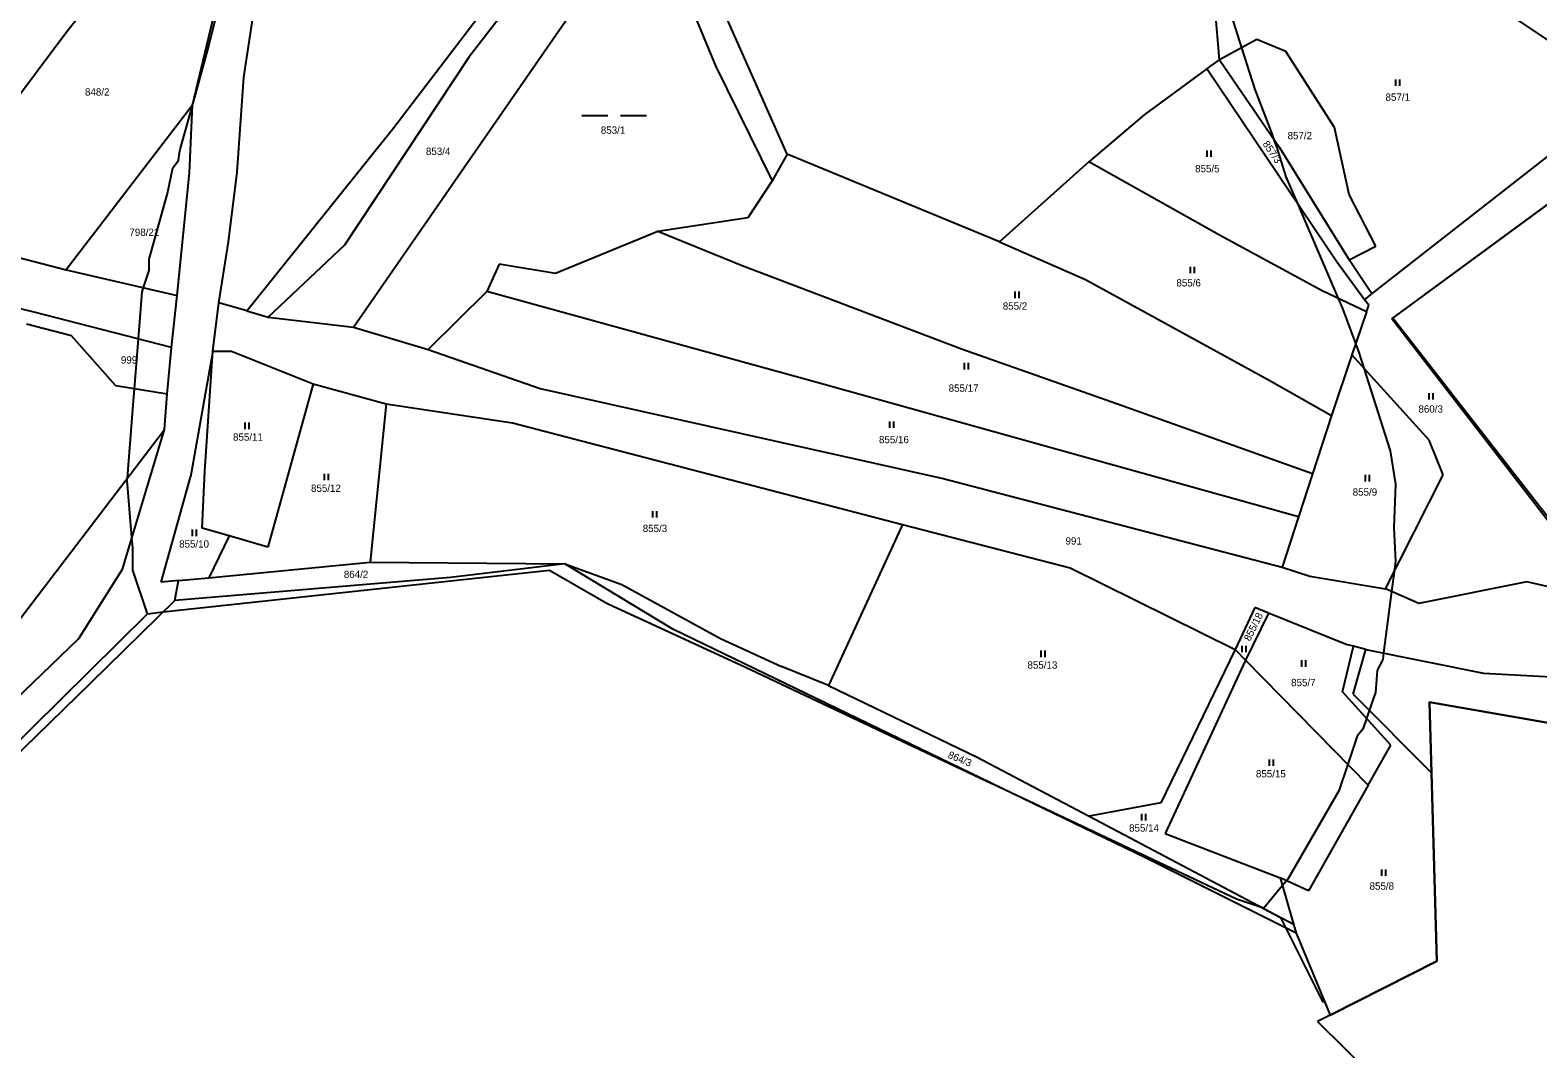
# Model space of a CAD drawing. Extents: x -749173 to -746119, y -1132678 to -1130338.
# Drawn here: x -747634.7 to -747283.8, y -1131870.4 to -1131633.3 of the extents above; entities that cross this region are included whole.
import ezdxf

# ---------------------------------------------------------------- set-up
doc = ezdxf.new("R2010")
doc.units = 0
for name, color, linetype in [('Vrstva 1', 7, 'Continuous'), ('Vrstva 18', 7, 'Continuous'), ('Vrstva 25', 7, 'Continuous'), ('Vrstva 52', 7, 'Continuous'), ('Vrstva 6', 7, 'Continuous')]:
    doc.layers.add(name, color=color, linetype=linetype)

msp = doc.modelspace()

# ---------------------------------------------------------------- linework, layer by layer
at = {"layer": 'Vrstva 1'}
for points in [[(-747357.88, -1131640.25), (-747361.08, -1131602.88)], [(-747596.84, -1131650.77), (-747587.27, -1131610.47)], [(-747550, -1131656.02), (-747518.42, -1131614.59)], [(-747512.18, -1131613.29), (-747532.53, -1131639.52)], [(-747458.45, -1131662.17), (-747478.47, -1131617.02)], [(-747484.66, -1131618.77), (-747475.19, -1131641.65)], [(-747559.41, -1131702.48), (-747504.69, -1131623.44)], [(-747584.9, -1131644.26), (-747582.84, -1131630.56)], [(-747290.52, -1131629.64), (-747262.86, -1131648.18)], [(-747349.2, -1131635.5), (-747357.88, -1131640.25)], [(-747342.45, -1131638.32), (-747349.2, -1131635.5)], [(-747532.53, -1131639.52), (-747561.47, -1131683.37)], [(-747331.11, -1131655.97), (-747342.45, -1131638.32)], [(-747475.19, -1131641.65), (-747462.01, -1131668.39)], [(-747360.8, -1131642.37), (-747375.43, -1131653.05)], [(-747360.8, -1131642.37), (-747357.88, -1131640.25)], [(-747330.67, -1131687.18), (-747360.8, -1131642.37)], [(-747357.88, -1131640.25), (-747343.93, -1131660.68)], [(-747586.46, -1131666.42), (-747584.9, -1131644.26)], [(-747322.41, -1131694.68), (-747262.86, -1131648.18)], [(-747597.6, -1131666.57), (-747596.84, -1131650.77)], [(-747375.43, -1131653.05), (-747388.27, -1131663.97)], [(-747584.22, -1131698.64), (-747550, -1131656.02)], [(-747327.7, -1131671.61), (-747331.11, -1131655.97)], [(-747317.79, -1131700.5), (-747257.91, -1131656.57)], [(-747458.45, -1131662.17), (-747462.01, -1131668.39)], [(-747409.06, -1131682.61), (-747458.45, -1131662.17)], [(-747388.27, -1131663.97), (-747409.06, -1131682.61)], [(-747357.85, -1131681.06), (-747388.27, -1131663.97)], [(-747343.93, -1131660.68), (-747327.68, -1131686.79)], [(-747600.45, -1131695.05), (-747597.6, -1131666.57)], [(-747588.52, -1131682.57), (-747586.46, -1131666.42)], [(-747462.01, -1131668.39), (-747467.61, -1131677.03)], [(-747321.53, -1131683.62), (-747327.7, -1131671.61)], [(-747467.61, -1131677.03), (-747488.58, -1131680.22)], [(-747660.92, -1131680.14), (-747626.3, -1131689.08)], [(-747488.58, -1131680.22), (-747512.4, -1131689.95)], [(-747334, -1131693.97), (-747357.85, -1131681.06)], [(-747590.72, -1131696.79), (-747588.52, -1131682.57)], [(-747561.47, -1131683.37), (-747579.28, -1131700.12)], [(-747409.06, -1131682.61), (-747389.09, -1131691.38)], [(-747327.68, -1131686.79), (-747321.53, -1131683.62)], [(-747525.49, -1131687.82), (-747528.4, -1131694.14)], [(-747512.4, -1131689.95), (-747525.49, -1131687.82)], [(-747324.17, -1131696.09), (-747330.67, -1131687.18)], [(-747322.41, -1131694.68), (-747327.68, -1131686.79)], [(-747633.7, -1131698.94), (-747668.66, -1131690.61)], [(-747626.3, -1131689.08), (-747600.45, -1131695.05)], [(-747389.09, -1131691.38), (-747346.34, -1131714.79)], [(-747601.8, -1131707.17), (-747600.45, -1131695.05)], [(-747528.4, -1131694.14), (-747542.02, -1131707.68)], [(-747323.64, -1131698.92), (-747334, -1131693.97)], [(-747324.17, -1131696.09), (-747322.41, -1131694.68)], [(-747601.8, -1131707.17), (-747633.7, -1131698.94)], [(-747592.13, -1131708.07), (-747590.72, -1131696.79)], [(-747584.22, -1131698.64), (-747590.72, -1131696.79)], [(-747584.22, -1131698.64), (-747579.28, -1131700.12)], [(-747323.64, -1131698.92), (-747327.11, -1131708.86)], [(-747323.11, -1131697.35), (-747324.17, -1131696.09)], [(-747323.64, -1131698.92), (-747323.11, -1131697.35)], [(-747625.03, -1131704.45), (-747635.51, -1131701.73)], [(-747579.28, -1131700.12), (-747559.41, -1131702.48)], [(-747559.41, -1131702.48), (-747542.02, -1131707.68)], [(-747267.01, -1131766.16), (-747317.79, -1131700.5)], [(-747614.7, -1131716.11), (-747625.03, -1131704.45)], [(-747602.77, -1131718.05), (-747601.8, -1131707.17)], [(-747592.13, -1131708.07), (-747594.14, -1131719.37)], [(-747592.13, -1131708.07), (-747587.81, -1131708.07)], [(-747587.81, -1131708.07), (-747568.8, -1131715.62)], [(-747542.02, -1131707.68), (-747515.95, -1131716.72)], [(-747327.11, -1131708.86), (-747331.81, -1131723.04)], [(-747309.11, -1131728.78), (-747327.11, -1131708.86)], [(-747602.77, -1131718.05), (-747614.7, -1131716.11)], [(-747568.8, -1131715.62), (-747551.8, -1131720.33)], [(-747346.34, -1131714.79), (-747331.81, -1131723.04)], [(-747603.39, -1131726.29), (-747602.77, -1131718.05)], [(-747594.14, -1131719.37), (-747597.33, -1131737.34)], [(-747515.95, -1131716.72), (-747422.18, -1131737.69)], [(-747551.8, -1131720.33), (-747522.4, -1131724.74)], [(-747331.81, -1131723.04), (-747336.24, -1131736.62)], [(-747646.92, -1131783.21), (-747603.39, -1131726.29)], [(-747613.18, -1131758.77), (-747603.39, -1131726.29)], [(-747522.4, -1131724.74), (-747431.62, -1131748.34)], [(-747305.82, -1131736.8), (-747309.11, -1131728.78)], [(-747604.15, -1131761.78), (-747597.33, -1131737.34)], [(-747422.18, -1131737.69), (-747343.31, -1131758.31)], [(-747336.24, -1131736.62), (-747339.49, -1131746.59)], [(-747319.28, -1131763.36), (-747305.82, -1131736.8)], [(-747339.49, -1131746.59), (-747343.31, -1131758.31)], [(-747431.62, -1131748.34), (-747392.64, -1131758.47)], [(-747623.35, -1131774.87), (-747613.18, -1131758.77)], [(-747593.06, -1131760.75), (-747555.53, -1131757.15)], [(-747555.53, -1131757.15), (-747510.21, -1131757.54)], [(-747510.21, -1131757.54), (-747536.87, -1131760.7)], [(-747510.21, -1131757.54), (-747496.95, -1131762.32)], [(-747485.07, -1131772.73), (-747510.21, -1131757.54)], [(-747392.64, -1131758.47), (-747354.27, -1131777.45)], [(-747343.31, -1131758.31), (-747336.85, -1131760.37)], [(-747600.14, -1131761.43), (-747604.15, -1131761.78)], [(-747536.87, -1131760.7), (-747601, -1131766.04)], [(-747601, -1131766.04), (-747600.14, -1131761.43)], [(-747600.14, -1131761.43), (-747593.06, -1131760.75)], [(-747496.95, -1131762.32), (-747474.01, -1131774.9)], [(-747336.85, -1131760.37), (-747319.28, -1131763.36)], [(-747286.37, -1131761.74), (-747311.5, -1131766.78)], [(-747267.01, -1131766.16), (-747286.37, -1131761.74)], [(-747311.5, -1131766.78), (-747319.28, -1131763.36)], [(-747601, -1131766.04), (-747620.58, -1131785.29)], [(-747349.64, -1131767.7), (-747354.27, -1131777.45)], [(-747346.48, -1131768.98), (-747349.64, -1131767.7)], [(-747328.4, -1131776.31), (-747346.48, -1131768.98)], [(-747375.12, -1131825.91), (-747485.07, -1131772.73)], [(-747651.15, -1131801.66), (-747623.35, -1131774.87)], [(-747474.01, -1131774.9), (-747459.79, -1131781.43)], [(-747326.7, -1131776.72), (-747328.4, -1131776.31)], [(-747354.27, -1131777.45), (-747351.83, -1131779.93)], [(-747329.29, -1131787.29), (-747326.7, -1131776.72)], [(-747326.78, -1131787.84), (-747323.8, -1131777.42)], [(-747323.8, -1131777.42), (-747326.7, -1131776.72)], [(-747323.8, -1131777.42), (-747296.48, -1131782.93)], [(-747448.86, -1131785.87), (-747459.79, -1131781.43)], [(-747351.83, -1131779.93), (-747323.26, -1131809)], [(-747296.48, -1131782.93), (-747266.19, -1131784.57)], [(-747620.58, -1131785.29), (-747683.25, -1131846.23)], [(-747448.86, -1131785.87), (-747414.25, -1131802.49)], [(-747318.03, -1131799.74), (-747329.29, -1131787.29)], [(-747326.78, -1131787.84), (-747308.51, -1131806.18)], [(-747274.72, -1131795.65), (-747308.97, -1131789.7)], [(-747308.97, -1131789.7), (-747308.51, -1131806.18)], [(-747323.26, -1131809), (-747318.03, -1131799.74)], [(-747414.25, -1131802.49), (-747388.18, -1131816.27)], [(-747308.51, -1131806.18), (-747307.27, -1131850)], [(-747323.26, -1131809), (-747337.16, -1131833.58)], [(-747388.18, -1131816.27), (-747340.66, -1131841.38)], [(-747340.05, -1131843.48), (-747375.12, -1131825.91)], [(-747337.16, -1131833.58), (-747343.77, -1131830.6)], [(-747343.77, -1131830.6), (-747340.66, -1131841.38)], [(-747340.66, -1131841.38), (-747340.05, -1131843.48)], [(-747340.05, -1131843.48), (-747332.1, -1131862.53)], [(-747307.27, -1131850), (-747332.1, -1131862.53)], [(-747332.1, -1131862.53), (-747335.11, -1131864.05)], [(-747335.11, -1131864.05), (-747316.12, -1131882.74)]]:
    msp.add_lwpolyline(points, dxfattribs=at)
at = {"layer": 'Vrstva 25'}
for p, q in [((-747316.92, -1131644.82), (-747316.92, -1131646.32)), ((-747315.92, -1131646.32), (-747315.92, -1131644.82)), ((-747506.25, -1131653.22), (-747500.25, -1131653.22)), ((-747497.25, -1131653.22), (-747491.25, -1131653.22)), ((-747360.81, -1131661.35), (-747360.81, -1131662.85)), ((-747359.81, -1131662.85), (-747359.81, -1131661.35)), ((-747364.67, -1131688.4), (-747364.67, -1131689.9)), ((-747363.67, -1131689.9), (-747363.67, -1131688.4)), ((-747405.52, -1131694.18), (-747405.52, -1131695.68)), ((-747404.52, -1131695.68), (-747404.52, -1131694.18)), ((-747417.28, -1131710.77), (-747417.28, -1131712.27)), ((-747416.28, -1131712.27), (-747416.28, -1131710.77)), ((-747309.18, -1131717.8), (-747309.18, -1131719.3)), ((-747308.18, -1131719.3), (-747308.18, -1131717.8)), ((-747584.72, -1131724.67), (-747584.72, -1131726.17)), ((-747583.72, -1131726.17), (-747583.72, -1131724.67)), ((-747434.66, -1131724.39), (-747434.66, -1131725.89)), ((-747433.66, -1131725.89), (-747433.66, -1131724.39)), ((-747566.2, -1131736.58), (-747566.2, -1131738.08)), ((-747565.2, -1131738.08), (-747565.2, -1131736.58)), ((-747324, -1131736.84), (-747324, -1131738.34)), ((-747323, -1131738.34), (-747323, -1131736.84)), ((-747489.84, -1131745.27), (-747489.84, -1131746.77)), ((-747488.84, -1131746.77), (-747488.84, -1131745.27)), ((-747596.93, -1131749.55), (-747596.93, -1131751.05)), ((-747595.93, -1131751.05), (-747595.93, -1131749.55)), ((-747399.45, -1131777.72), (-747399.45, -1131779.22)), ((-747398.45, -1131779.22), (-747398.45, -1131777.72)), ((-747352.67, -1131776.61), (-747352.67, -1131778.11)), ((-747351.67, -1131778.11), (-747351.67, -1131776.61)), ((-747338.8, -1131779.96), (-747338.8, -1131781.46)), ((-747337.8, -1131781.46), (-747337.8, -1131779.96)), ((-747346.32, -1131803.02), (-747346.32, -1131804.52)), ((-747345.32, -1131804.52), (-747345.32, -1131803.02)), ((-747376.06, -1131815.72), (-747376.06, -1131817.22)), ((-747375.06, -1131817.22), (-747375.06, -1131815.72)), ((-747320.16, -1131828.66), (-747320.16, -1131830.16)), ((-747319.16, -1131830.16), (-747319.16, -1131828.66))]:
    msp.add_line(p, q, dxfattribs=at)
at = {"layer": 'Vrstva 52'}
for points in [[(-747372.5, -1131565), (-747370.5, -1131575.62), (-747369.62, -1131580.75), (-747367.24, -1131593.37), (-747366.25, -1131598.62), (-747366.21, -1131598.74), (-747360.04, -1131615), (-747359, -1131617.75), (-747352.76, -1131637.44), (-747349.69, -1131647.12), (-747345.81, -1131657.25), (-747345.31, -1131658.66), (-747344.56, -1131660.75), (-747342.44, -1131667.5), (-747339.83, -1131673.56), (-747330.27, -1131695.75), (-747329.25, -1131698.12), (-747326.21, -1131706.29), (-747325.44, -1131708.37), (-747324.3, -1131711.97), (-747318.19, -1131731.25), (-747316.94, -1131739), (-747317.31, -1131749.12), (-747316.94, -1131756.87)], [(-747607.37, -1131769.12), (-747610.75, -1131759), (-747610.75, -1131753.87), (-747610.96, -1131751.39), (-747612.06, -1131738.12), (-747612.09, -1131737.67), (-747612.02, -1131737.57), (-747610.75, -1131721.5), (-747610.38, -1131716.81), (-747609.48, -1131705.19), (-747608.62, -1131694.25), (-747608.28, -1131693.24), (-747606.94, -1131689.25), (-747606.94, -1131686.62), (-747602.69, -1131671.37), (-747601.44, -1131665.37), (-747600.45, -1131664.06), (-747600.12, -1131663.62), (-747599.79, -1131661.42), (-747599.75, -1131661.12), (-747596.9, -1131650.85), (-747596.6, -1131649.76), (-747593.37, -1131638.12), (-747590.81, -1131628)], [(-747209.31, -1131766.12), (-747248.44, -1131768.75), (-747268, -1131764), (-747317.58, -1131700.34), (-747267.13, -1131663.33)], [(-747316.94, -1131756.87), (-747317.26, -1131759.38), (-747317.85, -1131763.99), (-747319.68, -1131778.25), (-747319.87, -1131779.75), (-747320.56, -1131781.12), (-747321.19, -1131782.37), (-747321.56, -1131787.5), (-747323.02, -1131791.62), (-747323.68, -1131793.49), (-747324.56, -1131796), (-747325.87, -1131797.62), (-747328.04, -1131804.13), (-747330.12, -1131810.37), (-747342, -1131830.87), (-747342.31, -1131831.26), (-747343.25, -1131832.39), (-747345.81, -1131835.5), (-747347.56, -1131837.62), (-747347.62, -1131837.7)], [(-747607.37, -1131769.12), (-747603.74, -1131768.73), (-747513.81, -1131759), (-747500.62, -1131766.62), (-747500, -1131766.91), (-747468.31, -1131781.5), (-747410.83, -1131808.64), (-747410.66, -1131808.72), (-747353.94, -1131835.5), (-747350.44, -1131836.66), (-747348.11, -1131837.44), (-747347.62, -1131837.7)], [(-747981.19, -1131822.75), (-747967.99, -1131825.11), (-747965.94, -1131825.48), (-747945.5, -1131829.12), (-747888.94, -1131839.37), (-747885.06, -1131840.12), (-747879.56, -1131841.5), (-747791.94, -1131859.37), (-747767.72, -1131863.73), (-747766.03, -1131864.04), (-747763.74, -1131864.45), (-747752.37, -1131866.5), (-747687.75, -1131878), (-747689.72, -1131868.02), (-747690.68, -1131863.17), (-747691.19, -1131860.62), (-747690.58, -1131855.27), (-747690.31, -1131852.87), (-747681.37, -1131842.25), (-747607.37, -1131769.12)], [(-747347.62, -1131837.7), (-747343.68, -1131839.79), (-747342.44, -1131842.28), (-747333.94, -1131859.37), (-747333.42, -1131859.37), (-747332.1, -1131862.53), (-747307.27, -1131850), (-747308.51, -1131806.18), (-747308.97, -1131789.7), (-747274.72, -1131795.65), (-747246.96, -1131810.99), (-747226.76, -1131829.48), (-747266.75, -1131882.75), (-747263.66, -1131883.58), (-747265.2, -1131885.54), (-747226.07, -1131896.73), (-747204.18, -1131909.18), (-747161.04, -1131934.49), (-747154.1, -1131938.56), (-747140.46, -1131946.56), (-747107.18, -1131952.81), (-747078.4, -1131964.27), (-747078.75, -1131965.25)]]:
    msp.add_lwpolyline(points, dxfattribs=at)
at = {"layer": 'Vrstva 6'}
for points in [[(-747626.14, -1131633.64), (-747573.17, -1131566.58)], [(-747660.92, -1131680.14), (-747626.14, -1131633.64)], [(-747596.84, -1131650.77), (-747626.3, -1131689.08)], [(-747468.94, -1131688.21), (-747488.58, -1131680.22)], [(-747417.95, -1131707.56), (-747468.94, -1131688.21)], [(-747451.3, -1131715.37), (-747528.4, -1131694.14)], [(-747593.98, -1131735.96), (-747592.13, -1131708.07)], [(-747381.64, -1131720.38), (-747417.95, -1131707.56)], [(-747568.8, -1131715.62), (-747579.31, -1131753.61)], [(-747339.49, -1131746.59), (-747451.3, -1131715.37)], [(-747551.8, -1131720.33), (-747555.53, -1131757.15)], [(-747336.24, -1131736.62), (-747381.64, -1131720.38)], [(-747594.62, -1131749.25), (-747593.98, -1131735.96)], [(-747588.32, -1131751.04), (-747594.62, -1131749.25)], [(-747588.32, -1131751.04), (-747593.06, -1131760.75)], [(-747579.31, -1131753.61), (-747588.32, -1131751.04)], [(-747431.62, -1131748.34), (-747448.86, -1131785.87)], [(-747346.48, -1131768.98), (-747351.83, -1131779.93)], [(-747354.27, -1131777.45), (-747371.51, -1131813.1)], [(-747351.83, -1131779.93), (-747370.56, -1131820.28)], [(-747371.51, -1131813.1), (-747388.18, -1131816.27)], [(-747370.56, -1131820.28), (-747343.77, -1131830.6)]]:
    msp.add_lwpolyline(points, dxfattribs=at)

# ---------------------------------------------------------------- texts
at = {"layer": 'Vrstva 18'}
for s, p in [('848/2', (-747621.89, -1131648.57)), ('857/1', (-747319.24, -1131649.78)), ('853/1', (-747501.85, -1131657.45)), ('857/2', (-747342.04, -1131658.72)), ('853/4', (-747542.55, -1131662.38)), ('855/5', (-747363.55, -1131666.41)), ('798/21', (-747611.56, -1131681.22)), ('855/6', (-747367.9, -1131692.99)), ('855/2', (-747408.32, -1131698.38)), ('999', (-747613.53, -1131710.92)), ('855/17', (-747420.91, -1131717.49)), ('860/3', (-747311.58, -1131722.34)), ('855/11', (-747587.45, -1131728.87)), ('855/16', (-747437.12, -1131729.46)), ('855/12', (-747569.3, -1131740.78)), ('855/9', (-747326.88, -1131741.66)), ('855/3', (-747492.1, -1131750.13)), ('991', (-747393.71, -1131753.04)), ('855/10', (-747599.99, -1131753.75)), ('864/2', (-747561.66, -1131760.82)), ('855/13', (-747402.56, -1131781.92)), ('855/7', (-747341.21, -1131785.99)), ('855/15', (-747349.4, -1131807.22)), ('855/14', (-747378.92, -1131819.83)), ('855/8', (-747322.95, -1131833.36))]:
    msp.add_text(s, height=1.7, dxfattribs=at).set_placement(p)
for s, rotation, p in [('857/3', 304.0724, (-747347.93, -1131659.83)), ('855/18', 63.6, (-747350.77, -1131775.66)), ('864/3', 337.4452, (-747421.24, -1131802.6))]:
    msp.add_text(s, height=1.7, rotation=rotation, dxfattribs=at).set_placement(p)

doc.saveas('drawing.dxf')
